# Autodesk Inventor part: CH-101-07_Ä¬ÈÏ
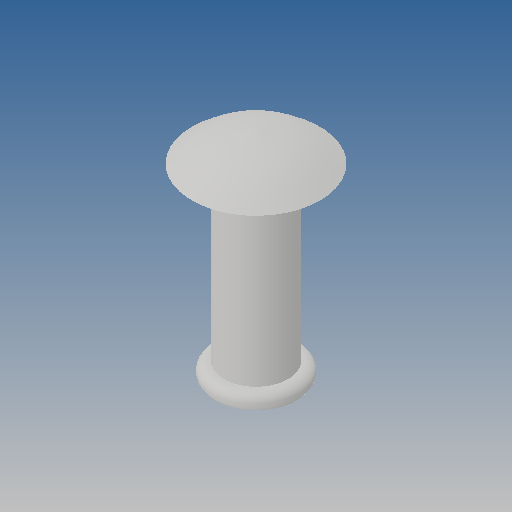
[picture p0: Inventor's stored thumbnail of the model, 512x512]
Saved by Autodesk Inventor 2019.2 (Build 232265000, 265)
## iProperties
Created: 2010-06
Part Number: CH-101-07_Ä¬ÈÏ
Material: Ogólny
Document SubType Name: Modeling
Designer: CADENGINEERING4
Density: 1 g/cm^3
Appearance: Domyślna
Author: CADENGINEERING4
Revision Number: ÈÎºÎ
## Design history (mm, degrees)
feature "NONE"
node "Bryła1"
